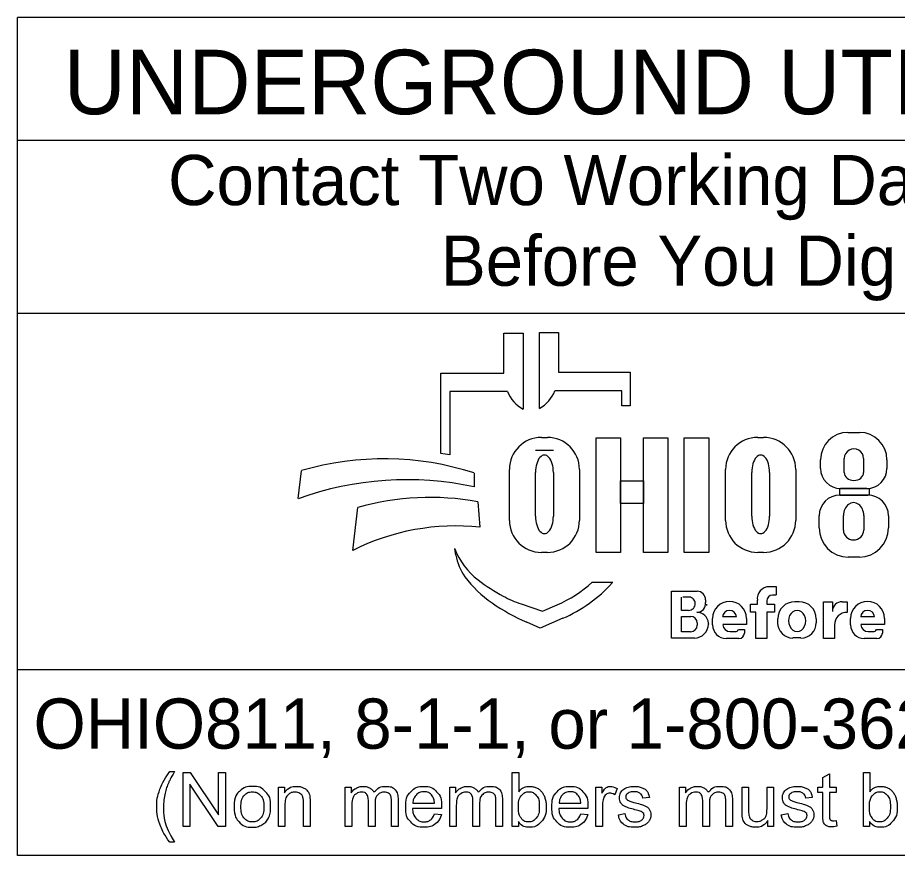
# Model space of a CAD drawing. Extents: x 0 to 34, y 0 to 22.
# Drawn here: x 14.876 to 17.33, y 5.729 to 8.066 of the extents above; entities that cross this region are included whole.
import ezdxf

# ---------------------------------------------------------------- set-up
doc = ezdxf.new("R2010")
doc.units = 0
doc.layers.add('GM_X_Adjacent_County', color=7, linetype='Continuous')
doc.layers.add('GM_X_Township', color=7, linetype='Continuous')

msp = doc.modelspace()

# ---------------------------------------------------------------- linework, layer by layer
at = {"layer": 'GM_X_Adjacent_County'}
for p, q in [((16.2322, 7.0744), (16.2322, 7.1859)), ((16.2322, 7.1859), (16.2858, 7.1859)), ((16.2858, 7.1859), (16.2858, 6.9738)), ((16.3315, 6.9761), (16.3315, 7.1882)), ((16.3315, 7.1882), (16.3851, 7.1882)), ((16.3851, 7.1882), (16.3851, 7.0767)), ((16.0562, 6.8505), (16.0562, 7.0744)), ((16.0562, 7.0744), (16.2322, 7.0744)), ((16.3851, 7.0767), (16.5844, 7.0767)), ((16.5844, 7.0767), (16.5844, 6.9829)), ((16.0815, 7.0229), (16.0815, 6.8461)), ((16.2426, 7.0229), (16.0815, 7.0229)), ((16.5611, 7.0253), (16.3747, 7.0253)), ((16.5611, 6.9829), (16.5611, 7.0253)), ((16.5844, 6.9829), (16.5611, 6.9829)), ((16.3372, 6.8952), (16.3537, 6.8952)), ((16.9402, 6.8952), (16.9568, 6.8952)), ((17.1918, 6.9092), (17.2245, 6.9092)), ((16.3705, 6.8582), (16.3207, 6.8582)), ((17.1155, 6.8086), (17.1155, 6.8329)), ((17.1816, 6.7972), (17.1816, 6.8365)), ((17.2358, 6.8365), (17.2358, 6.7972)), ((17.3008, 6.8329), (17.3008, 6.8086)), ((15.6589, 6.7242), (15.6683, 6.8023)), ((16.2477, 6.6637), (16.2477, 6.8057)), ((16.3206, 6.6751), (16.3206, 6.7975)), ((16.3704, 6.7975), (16.3704, 6.6751)), ((16.4432, 6.8057), (16.4432, 6.6637)), ((16.8508, 6.6637), (16.8508, 6.8057)), ((16.9237, 6.6751), (16.9237, 6.7975)), ((16.9735, 6.7975), (16.9735, 6.6751)), ((17.0462, 6.8057), (17.0462, 6.6637)), ((16.1495, 6.7958), (16.1495, 6.757)), ((17.2448, 6.7526), (17.1715, 6.7526)), ((17.1696, 6.7343), (17.247, 6.7343)), ((15.8107, 6.5797), (15.8254, 6.6998)), ((16.1595, 6.7152), (16.1657, 6.6443)), ((17.1118, 6.6424), (17.1118, 6.6764)), ((17.1792, 6.6364), (17.1792, 6.6773)), ((17.2361, 6.6773), (17.2361, 6.6364)), ((17.3049, 6.6764), (17.3049, 6.6424)), ((16.0984, 6.5668), (16.0953, 6.5847)), ((16.3537, 6.5743), (16.3372, 6.5743)), ((16.9568, 6.5743), (16.9402, 6.5743)), ((17.2239, 6.5614), (17.1927, 6.5614)), ((16.4787, 6.4909), (16.5361, 6.4909)), ((16.9726, 6.4787), (16.992, 6.4787)), ((16.992, 6.4787), (16.992, 6.4557)), ((16.7, 6.3351), (16.7, 6.4659)), ((16.7, 6.4659), (16.7712, 6.4659)), ((16.992, 6.4552), (16.9819, 6.4552)), ((16.2803, 6.4305), (16.3397, 6.41)), ((16.7279, 6.4124), (16.7279, 6.4493)), ((16.7531, 6.4493), (16.7319, 6.4493)), ((16.7949, 6.4421), (16.7949, 6.4342)), ((16.92, 6.4073), (16.92, 6.4303)), ((16.92, 6.4303), (16.9393, 6.4303)), ((16.9393, 6.4303), (16.9393, 6.4407)), ((16.9654, 6.4387), (16.9654, 6.4303)), ((16.9654, 6.4303), (16.9869, 6.4303)), ((16.9869, 6.4303), (16.9869, 6.4073)), ((17.0438, 6.4369), (17.0559, 6.4369)), ((17.124, 6.3339), (17.124, 6.4366)), ((17.124, 6.4366), (17.1486, 6.4366)), ((17.1486, 6.4366), (17.1486, 6.4098)), ((17.1758, 6.4366), (17.1897, 6.4366)), ((17.1897, 6.4366), (17.1897, 6.407)), ((16.3397, 6.41), (16.3807, 6.4278)), ((16.7474, 6.4124), (16.7279, 6.4124)), ((16.9349, 6.4073), (16.92, 6.4073)), ((16.9349, 6.3339), (16.9349, 6.4073)), ((16.9869, 6.4073), (16.9654, 6.4073)), ((16.9654, 6.4073), (16.9654, 6.3339)), ((16.3969, 6.3905), (16.3337, 6.363)), ((16.7279, 6.353), (16.7279, 6.3958)), ((16.7279, 6.3958), (16.7535, 6.3958)), ((16.8145, 6.3719), (16.8145, 6.3903)), ((16.8811, 6.3943), (16.8426, 6.3943)), ((16.9091, 6.3903), (16.9091, 6.3727)), ((16.996, 6.3782), (16.996, 6.389)), ((17.1037, 6.389), (17.1037, 6.3782)), ((17.1994, 6.3719), (17.1994, 6.3903)), ((17.266, 6.3943), (17.2275, 6.3943)), ((17.294, 6.3903), (17.294, 6.3727)), ((16.3337, 6.363), (16.2963, 6.3795)), ((16.7716, 6.3777), (16.7716, 6.3713)), ((16.803, 6.3748), (16.803, 6.3745)), ((16.9091, 6.3727), (16.8426, 6.3727)), ((16.8863, 6.359), (16.9031, 6.359)), ((16.9031, 6.359), (16.9031, 6.3492)), ((17.1545, 6.3721), (17.1545, 6.3339)), ((17.294, 6.3727), (17.2276, 6.3727)), ((17.2712, 6.359), (17.288, 6.359)), ((17.288, 6.359), (17.288, 6.3492)), ((16.7636, 6.3351), (16.7, 6.3351)), ((16.7532, 6.353), (16.7279, 6.353)), ((16.8879, 6.3339), (16.8525, 6.3339)), ((16.8636, 6.3534), (16.8777, 6.3534)), ((16.9654, 6.3339), (16.9349, 6.3339)), ((17.0609, 6.3355), (17.0387, 6.3355)), ((17.1545, 6.3339), (17.124, 6.3339)), ((17.2728, 6.3339), (17.2374, 6.3339)), ((17.2485, 6.3534), (17.2626, 6.3534))]:
    msp.add_line(p, q, dxfattribs=at)
for points in [[(16.4896, 6.8942), (16.5576, 6.8942), (16.5576, 6.5742), (16.4896, 6.5742)], [(16.6218, 6.8942), (16.6897, 6.8942), (16.6897, 6.5742), (16.6218, 6.5742)], [(16.7351, 6.8942), (16.8039, 6.8942), (16.8039, 6.5742), (16.7351, 6.5742)], [(16.5576, 6.7743), (16.6218, 6.7743), (16.6218, 6.7103), (16.5576, 6.7103)], [(17.1693, 6.7526), (17.251, 6.7526), (17.251, 6.7342), (17.1693, 6.7342)]]:
    msp.add_lwpolyline(points, close=True, dxfattribs=at)
for points in [[(15.3008, 5.9627), (15.314, 5.9627)], [(15.3375, 5.81), (15.3375, 5.9602), (15.3579, 5.9602), (15.4369, 5.8422), (15.4369, 5.9602), (15.4559, 5.9602), (15.4559, 5.81), (15.4355, 5.81), (15.3565, 5.928), (15.3565, 5.81), (15.3375, 5.81)], [(16.273, 5.81), (16.2559, 5.81), (16.2559, 5.9602), (16.2744, 5.9602), (16.2744, 5.9067)], [(17.1219, 5.8419), (17.1219, 5.9046), (17.1083, 5.9046), (17.1083, 5.9189), (17.1219, 5.9189), (17.1219, 5.9458), (17.1404, 5.9569), (17.1404, 5.9189), (17.1588, 5.9189), (17.1588, 5.9046), (17.1404, 5.9046), (17.1404, 5.8408)], [(17.2521, 5.81), (17.235, 5.81), (17.235, 5.9602), (17.2534, 5.9602), (17.2534, 5.9067)], [(15.6035, 5.81), (15.6035, 5.9189), (15.6201, 5.9189), (15.6201, 5.9034)], [(15.7899, 5.81), (15.7899, 5.9189), (15.8064, 5.9189), (15.8064, 5.9035)], [(16.0813, 5.81), (16.0813, 5.9189), (16.0978, 5.9189), (16.0978, 5.9035)], [(16.4891, 5.81), (16.4891, 5.9189), (16.5057, 5.9189), (16.5057, 5.9024)], [(16.5481, 5.9154), (16.5417, 5.8983)], [(16.7223, 5.81), (16.7223, 5.9189), (16.7388, 5.9189), (16.7388, 5.9035)], [(16.8966, 5.8515), (16.8966, 5.9189), (16.915, 5.9189), (16.915, 5.8585)], [(16.9663, 5.8606), (16.9663, 5.9189), (16.9847, 5.9189), (16.9847, 5.81), (16.9682, 5.81)], [(16.6381, 5.8907), (16.62, 5.8883)], [(17.0926, 5.8907), (17.0746, 5.8883)], [(15.6219, 5.8694), (15.6219, 5.81), (15.6035, 5.81)], [(15.6918, 5.8769), (15.6918, 5.81), (15.6734, 5.81), (15.6734, 5.8762)], [(15.8083, 5.8664), (15.8083, 5.81), (15.7899, 5.81)], [(15.873, 5.8732), (15.873, 5.81), (15.8546, 5.81), (15.8546, 5.8807)], [(15.9374, 5.8847), (15.9374, 5.81), (15.919, 5.81), (15.919, 5.8785)], [(15.9785, 5.8748), (16.0393, 5.8748)], [(16.0997, 5.8664), (16.0997, 5.81), (16.0813, 5.81)], [(16.1644, 5.8732), (16.1644, 5.81), (16.1459, 5.81), (16.1459, 5.8807)], [(16.2288, 5.8847), (16.2288, 5.81), (16.2104, 5.81), (16.2104, 5.8785)], [(16.3865, 5.8748), (16.4473, 5.8748)], [(16.5075, 5.867), (16.5075, 5.81), (16.4891, 5.81)], [(16.7407, 5.8664), (16.7407, 5.81), (16.7223, 5.81)], [(16.8054, 5.8732), (16.8054, 5.81), (16.7869, 5.81), (16.7869, 5.8807)], [(16.8698, 5.8847), (16.8698, 5.81), (16.8514, 5.81), (16.8514, 5.8785)], [(16.0587, 5.8597), (15.9775, 5.8597)], [(16.0391, 5.8452), (16.0581, 5.8428)], [(16.4666, 5.8597), (16.3855, 5.8597)], [(16.4471, 5.8452), (16.4661, 5.8428)], [(16.5517, 5.8425), (16.5699, 5.8454)], [(17.0062, 5.8425), (17.0244, 5.8454)], [(16.273, 5.8236), (16.273, 5.81)], [(16.9682, 5.81), (16.9682, 5.8261)], [(17.1588, 5.8265), (17.1614, 5.8102)], [(17.2521, 5.8236), (17.2521, 5.81)], [(15.314, 5.7658), (15.3008, 5.7658)]]:
    msp.add_lwpolyline(points, dxfattribs=at)
for centre, radius, start, end in [((16.334, 7.0597), 0.0985, 201.9296, 240.7469), ((16.2834, 7.062), 0.0985, 299.2531, 338.0704), ((16.3372, 6.8057), 0.0895, 90, 180), ((16.3537, 6.8057), 0.0895, 0, 90), ((16.9402, 6.8057), 0.0895, 90, 180), ((16.9568, 6.8057), 0.0895, 0, 90), ((17.1918, 6.8329), 0.0763, 90, 180), ((17.2245, 6.8329), 0.0763, 0, 90), ((15.9281, 6.0415), 0.8191, 79.2074, 81.0007), ((15.8983, 6.0163), 0.8191, 72.1402, 106.3144), ((17.1715, 6.8086), 0.056, 180, 270), ((17.2448, 6.8086), 0.056, 270, 0), ((15.9614, 5.8851), 0.8919, 77.8238, 109.8274), ((16.0253, 5.9955), 0.7322, 79.44, 105.8467), ((17.1696, 6.6764), 0.0579, 90, 180), ((17.247, 6.6764), 0.0579, 0, 90), ((16.3372, 6.6637), 0.0895, 180, 270), ((16.3537, 6.6637), 0.0895, 270, 0), ((16.9402, 6.6637), 0.0895, 180, 270), ((16.9568, 6.6637), 0.0895, 270, 0), ((16.0974, 6.0123), 0.6357, 83.8248, 116.8021), ((17.1927, 6.6424), 0.081, 180, 270), ((17.2239, 6.6424), 0.081, 270, 0), ((16.2827, 6.6568), 0.2008, 201.0457, 232.5314), ((16.2397, 6.5909), 0.1433, 189.6817, 216.0884), ((16.3734, 6.6883), 0.3088, 216.0884, 235.7167), ((16.4753, 6.908), 0.5173, 232.5314, 241.794), ((16.2373, 6.7583), 0.3602, 293.4582, 312.0712), ((16.2373, 6.7583), 0.401, 293.4582, 317.8286), ((16.9726, 6.4451), 0.0335, 90, 187.5187), ((16.7712, 6.4421), 0.0238, 0, 90), ((16.9819, 6.4387), 0.0165, 90, 180), ((16.5399, 6.9326), 0.6044, 235.7167, 246.2325), ((16.3901, 6.7492), 0.3371, 241.794, 250.9821), ((16.7474, 6.4311), 0.0187, 270, 2.0582), ((16.7492, 6.4324), 0.0169, 357.8325, 90), ((16.7708, 6.4314), 0.0243, 270, 6.6529), ((16.7813, 6.4299), 0.0175, 347.4023, 0), ((16.8618, 6.3903), 0.0473, 0, 180), ((17.0438, 6.389), 0.0478, 90, 180), ((17.0559, 6.389), 0.0478, 0, 90), ((17.1755, 6.4098), 0.0269, 89.2449, 180), ((17.2467, 6.3903), 0.0473, 0, 180), ((16.7709, 6.375), 0.0321, 4.0748, 90), ((16.8618, 6.3933), 0.0193, 2.9632, 177.0368), ((17.1895, 6.3721), 0.0349, 89.6033, 180), ((17.2468, 6.3933), 0.0193, 2.9632, 177.0368), ((16.7535, 6.3777), 0.0181, 0, 90), ((16.77, 6.3748), 0.033, 0, 11.7502), ((16.7532, 6.3713), 0.0184, 270, 0), ((16.7636, 6.3745), 0.0393, 270, 0), ((16.8525, 6.3719), 0.038, 180, 270), ((16.8636, 6.3744), 0.021, 184.827, 270), ((16.8777, 6.3628), 0.00938, 270, 335.9979), ((17.0387, 6.3782), 0.0428, 180, 270), ((17.0609, 6.3782), 0.0428, 270, 0), ((17.2374, 6.3719), 0.038, 180, 270), ((17.2485, 6.3744), 0.021, 184.827, 270), ((17.2626, 6.3628), 0.00938, 270, 335.9979), ((16.8879, 6.3492), 0.0152, 270, 0), ((17.2728, 6.3492), 0.0152, 270, 0)]:
    msp.add_arc(centre, radius, start, end, dxfattribs=at)
for centre, major_axis, ratio, start_param, end_param in [((17.2087, 6.8365), (0.0271, 0), 0.969373, 0, 3.141593), ((16.3455, 6.7975), (0, 0.0484), 0.514403, 4.712389, 7.853982), ((16.9486, 6.7975), (0, 0.0484), 0.514403, 4.712389, 7.853982), ((17.2087, 6.7972), (0.0271, 0), 0.818453, 3.141593, 6.283185), ((17.2077, 6.6773), (0, 0.0358), 0.794529, 4.712389, 7.853982), ((16.3455, 6.6751), (0, 0.0484), 0.514403, 1.570796, 4.712389), ((16.9486, 6.6751), (0, 0.0484), 0.514403, 1.570796, 4.712389), ((17.2077, 6.6364), (0.0284, 0), 0.959837, 3.141593, 6.283185), ((17.0503, 6.3836), (0, 0.029), 0.832186, 4.712389, 7.853982), ((17.0503, 6.3836), (0, 0.0302), 0.797287, 1.570796, 4.712389)]:
    msp.add_ellipse(centre, major_axis=major_axis, ratio=ratio, start_param=start_param, end_param=end_param, dxfattribs=at)
for points in [[(15.3008, 5.7658), (15.2855, 5.7851), (15.275, 5.8109), (15.2644, 5.8367), (15.2644, 5.8644), (15.2644, 5.8887), (15.2723, 5.9111), (15.2815, 5.937), (15.3008, 5.9627)], [(15.314, 5.9627), (15.3016, 5.9414), (15.2976, 5.9323), (15.2914, 5.9181), (15.2878, 5.9028), (15.2834, 5.8836), (15.2834, 5.8643), (15.2834, 5.815), (15.314, 5.7658)], [(15.48, 5.8644), (15.48, 5.8946), (15.4968, 5.9092), (15.5108, 5.9213), (15.531, 5.9213), (15.5534, 5.9213), (15.5676, 5.9066), (15.5819, 5.8919), (15.5819, 5.866), (15.5819, 5.845), (15.5756, 5.833), (15.5693, 5.8209), (15.5572, 5.8143), (15.5452, 5.8076), (15.531, 5.8076), (15.5082, 5.8076), (15.4941, 5.8223), (15.48, 5.8369), (15.48, 5.8644)], [(15.6201, 5.9034), (15.6321, 5.9213), (15.6547, 5.9213), (15.6645, 5.9213), (15.6728, 5.9177), (15.681, 5.9142), (15.6851, 5.9085), (15.6892, 5.9027), (15.6908, 5.8948), (15.6918, 5.8897), (15.6918, 5.8769)], [(15.8064, 5.9035), (15.8115, 5.9115), (15.82, 5.9164), (15.8285, 5.9213), (15.8394, 5.9213), (15.8515, 5.9213), (15.8592, 5.9162), (15.8669, 5.9112), (15.8701, 5.9022), (15.8831, 5.9213), (15.9038, 5.9213), (15.92, 5.9213), (15.9287, 5.9123), (15.9374, 5.9033), (15.9374, 5.8847)], [(16.0581, 5.8428), (16.0536, 5.8261), (16.0414, 5.8168), (16.0293, 5.8076), (16.0103, 5.8076), (15.9865, 5.8076), (15.9725, 5.8223), (15.9585, 5.837), (15.9585, 5.8635), (15.9585, 5.891), (15.9726, 5.9061), (15.9868, 5.9213), (16.0093, 5.9213), (16.0311, 5.9213), (16.0449, 5.9064), (16.0588, 5.8916), (16.0588, 5.8646), (16.0588, 5.863), (16.0587, 5.8597)], [(16.0978, 5.9035), (16.1029, 5.9115), (16.1114, 5.9164), (16.1199, 5.9213), (16.1308, 5.9213), (16.1428, 5.9213), (16.1506, 5.9162), (16.1583, 5.9112), (16.1615, 5.9022), (16.1744, 5.9213), (16.1951, 5.9213), (16.2114, 5.9213), (16.2201, 5.9123), (16.2288, 5.9033), (16.2288, 5.8847)], [(16.2744, 5.9067), (16.286, 5.9213), (16.3042, 5.9213), (16.3142, 5.9213), (16.3232, 5.9172), (16.3321, 5.9132), (16.3379, 5.9059), (16.3437, 5.8985), (16.347, 5.8882), (16.3502, 5.8778), (16.3502, 5.8661), (16.3502, 5.8381), (16.3364, 5.8229), (16.3226, 5.8076), (16.3032, 5.8076), (16.284, 5.8076), (16.273, 5.8236)], [(16.4661, 5.8428), (16.4616, 5.8261), (16.4494, 5.8168), (16.4373, 5.8076), (16.4183, 5.8076), (16.3944, 5.8076), (16.3805, 5.8223), (16.3665, 5.837), (16.3665, 5.8635), (16.3665, 5.891), (16.3806, 5.9061), (16.3948, 5.9213), (16.4173, 5.9213), (16.4391, 5.9213), (16.4529, 5.9064), (16.4667, 5.8916), (16.4667, 5.8646), (16.4667, 5.863), (16.4666, 5.8597)], [(16.5057, 5.9024), (16.512, 5.9139), (16.5174, 5.9176), (16.5227, 5.9213), (16.5292, 5.9213), (16.5385, 5.9213), (16.5481, 5.9154)], [(16.5699, 5.8454), (16.5714, 5.8344), (16.5784, 5.8286), (16.5855, 5.8227), (16.5981, 5.8227), (16.6109, 5.8227), (16.617, 5.8279), (16.6232, 5.8331), (16.6232, 5.8401), (16.6232, 5.8463), (16.6177, 5.8499), (16.6139, 5.8524), (16.5989, 5.8562), (16.5786, 5.8613), (16.5707, 5.865), (16.5629, 5.8688), (16.5588, 5.8754), (16.5548, 5.882), (16.5548, 5.8899), (16.5548, 5.8972), (16.5581, 5.9034), (16.5614, 5.9096), (16.5672, 5.9137), (16.5715, 5.9169), (16.5789, 5.9191), (16.5864, 5.9213), (16.5949, 5.9213), (16.6077, 5.9213), (16.6174, 5.9176), (16.6271, 5.9139), (16.6317, 5.9076), (16.6363, 5.9013), (16.6381, 5.8907)], [(16.7388, 5.9035), (16.7439, 5.9115), (16.7524, 5.9164), (16.7609, 5.9213), (16.7718, 5.9213), (16.7838, 5.9213), (16.7916, 5.9162), (16.7993, 5.9112), (16.8025, 5.9022), (16.8154, 5.9213), (16.8361, 5.9213), (16.8524, 5.9213), (16.8611, 5.9123), (16.8698, 5.9033), (16.8698, 5.8847)], [(17.0244, 5.8454), (17.026, 5.8344), (17.033, 5.8286), (17.04, 5.8227), (17.0527, 5.8227), (17.0654, 5.8227), (17.0716, 5.8279), (17.0778, 5.8331), (17.0778, 5.8401), (17.0778, 5.8463), (17.0723, 5.8499), (17.0685, 5.8524), (17.0534, 5.8562), (17.0331, 5.8613), (17.0253, 5.865), (17.0174, 5.8688), (17.0134, 5.8754), (17.0093, 5.882), (17.0093, 5.8899), (17.0093, 5.8972), (17.0127, 5.9034), (17.016, 5.9096), (17.0217, 5.9137), (17.026, 5.9169), (17.0335, 5.9191), (17.0409, 5.9213), (17.0494, 5.9213), (17.0623, 5.9213), (17.072, 5.9176), (17.0817, 5.9139), (17.0863, 5.9076), (17.0909, 5.9013), (17.0926, 5.8907)], [(17.2534, 5.9067), (17.2651, 5.9213), (17.2832, 5.9213), (17.2933, 5.9213), (17.3022, 5.9172), (17.3112, 5.9132), (17.317, 5.9059), (17.3228, 5.8985), (17.326, 5.8882), (17.3293, 5.8778), (17.3293, 5.8661), (17.3293, 5.8381), (17.3155, 5.8229), (17.3016, 5.8076), (17.2823, 5.8076), (17.263, 5.8076), (17.2521, 5.8236)], [(15.499, 5.8644), (15.499, 5.8435), (15.5081, 5.8331), (15.5172, 5.8227), (15.531, 5.8227), (15.5447, 5.8227), (15.5538, 5.8332), (15.5629, 5.8436), (15.5629, 5.865), (15.5629, 5.8852), (15.5537, 5.8956), (15.5446, 5.906), (15.531, 5.906), (15.5172, 5.906), (15.5081, 5.8957), (15.499, 5.8853), (15.499, 5.8644)], [(15.6734, 5.8762), (15.6734, 5.8874), (15.6713, 5.893), (15.6691, 5.8986), (15.6636, 5.9019), (15.6582, 5.9052), (15.6508, 5.9052), (15.639, 5.9052), (15.6305, 5.8978), (15.6219, 5.8903), (15.6219, 5.8694)], [(15.8546, 5.8807), (15.8546, 5.893), (15.8501, 5.8991), (15.8455, 5.9052), (15.8353, 5.9052), (15.8275, 5.9052), (15.8209, 5.9011), (15.8143, 5.897), (15.8113, 5.8892), (15.8083, 5.8813), (15.8083, 5.8664)], [(15.919, 5.8785), (15.919, 5.8896), (15.9172, 5.8944), (15.9154, 5.8993), (15.9107, 5.9023), (15.906, 5.9052), (15.8996, 5.9052), (15.8882, 5.9052), (15.8806, 5.8976), (15.873, 5.89), (15.873, 5.8732)], [(16.0393, 5.8748), (16.0381, 5.8886), (16.0323, 5.8955), (16.0235, 5.9062), (16.0095, 5.9062), (15.9968, 5.9062), (15.9881, 5.8976), (15.9795, 5.8891), (15.9785, 5.8748)], [(16.1459, 5.8807), (16.1459, 5.893), (16.1414, 5.8991), (16.1369, 5.9052), (16.1267, 5.9052), (16.1189, 5.9052), (16.1123, 5.9011), (16.1056, 5.897), (16.1027, 5.8892), (16.0997, 5.8813), (16.0997, 5.8664)], [(16.2104, 5.8785), (16.2104, 5.8896), (16.2086, 5.8944), (16.2068, 5.8993), (16.2021, 5.9023), (16.1974, 5.9052), (16.191, 5.9052), (16.1795, 5.9052), (16.1719, 5.8976), (16.1644, 5.89), (16.1644, 5.8732)], [(16.2728, 5.8653), (16.2728, 5.8457), (16.2781, 5.837), (16.2868, 5.8227), (16.3016, 5.8227), (16.3137, 5.8227), (16.3225, 5.8332), (16.3312, 5.8437), (16.3312, 5.8645), (16.3312, 5.8859), (16.3228, 5.896), (16.3144, 5.9062), (16.3024, 5.9062), (16.2903, 5.9062), (16.2816, 5.8956), (16.2728, 5.8851), (16.2728, 5.8653)], [(16.4473, 5.8748), (16.4461, 5.8886), (16.4403, 5.8955), (16.4315, 5.9062), (16.4175, 5.9062), (16.4048, 5.9062), (16.3961, 5.8976), (16.3874, 5.8891), (16.3865, 5.8748)], [(16.5417, 5.8983), (16.5349, 5.9023), (16.5282, 5.9023), (16.5222, 5.9023), (16.5174, 5.8986), (16.5126, 5.895), (16.5106, 5.8885), (16.5075, 5.8787), (16.5075, 5.867)], [(16.62, 5.8883), (16.6188, 5.8967), (16.6129, 5.9014), (16.607, 5.9062), (16.5962, 5.9062), (16.5835, 5.9062), (16.578, 5.9019), (16.5726, 5.8977), (16.5726, 5.8921), (16.5726, 5.8885), (16.5749, 5.8856), (16.5771, 5.8827), (16.5819, 5.8807), (16.5847, 5.8797), (16.5982, 5.876), (16.6178, 5.8708), (16.6256, 5.8674), (16.6333, 5.8641), (16.6378, 5.8578), (16.6422, 5.8514), (16.6422, 5.842), (16.6422, 5.8328), (16.6368, 5.8247), (16.6314, 5.8165), (16.6212, 5.8121), (16.6111, 5.8076), (16.5983, 5.8076), (16.577, 5.8076), (16.5659, 5.8164), (16.5547, 5.8252), (16.5517, 5.8425)], [(16.7869, 5.8807), (16.7869, 5.893), (16.7824, 5.8991), (16.7779, 5.9052), (16.7677, 5.9052), (16.7599, 5.9052), (16.7533, 5.9011), (16.7466, 5.897), (16.7437, 5.8892), (16.7407, 5.8813), (16.7407, 5.8664)], [(16.8514, 5.8785), (16.8514, 5.8896), (16.8496, 5.8944), (16.8478, 5.8993), (16.8431, 5.9023), (16.8384, 5.9052), (16.832, 5.9052), (16.8205, 5.9052), (16.8129, 5.8976), (16.8054, 5.89), (16.8054, 5.8732)], [(17.0746, 5.8883), (17.0733, 5.8967), (17.0674, 5.9014), (17.0615, 5.9062), (17.0508, 5.9062), (17.038, 5.9062), (17.0326, 5.9019), (17.0272, 5.8977), (17.0272, 5.8921), (17.0272, 5.8885), (17.0294, 5.8856), (17.0317, 5.8827), (17.0365, 5.8807), (17.0393, 5.8797), (17.0528, 5.876), (17.0724, 5.8708), (17.0802, 5.8674), (17.0879, 5.8641), (17.0923, 5.8578), (17.0968, 5.8514), (17.0968, 5.842), (17.0968, 5.8328), (17.0914, 5.8247), (17.086, 5.8165), (17.0758, 5.8121), (17.0657, 5.8076), (17.0528, 5.8076), (17.0316, 5.8076), (17.0204, 5.8164), (17.0093, 5.8252), (17.0062, 5.8425)], [(17.2518, 5.8653), (17.2518, 5.8457), (17.2571, 5.837), (17.2658, 5.8227), (17.2807, 5.8227), (17.2927, 5.8227), (17.3015, 5.8332), (17.3103, 5.8437), (17.3103, 5.8645), (17.3103, 5.8859), (17.3019, 5.896), (17.2934, 5.9062), (17.2815, 5.9062), (17.2694, 5.9062), (17.2606, 5.8956), (17.2518, 5.8851), (17.2518, 5.8653)], [(15.9775, 5.8597), (15.9785, 5.8418), (15.9876, 5.8322), (15.9968, 5.8227), (16.0104, 5.8227), (16.0205, 5.8227), (16.0277, 5.8281), (16.0349, 5.8334), (16.0391, 5.8452)], [(16.3855, 5.8597), (16.3865, 5.8418), (16.3956, 5.8322), (16.4048, 5.8227), (16.4184, 5.8227), (16.4285, 5.8227), (16.4357, 5.8281), (16.4429, 5.8334), (16.4471, 5.8452)], [(16.9682, 5.8261), (16.9555, 5.8076), (16.9337, 5.8076), (16.9241, 5.8076), (16.9158, 5.8113), (16.9074, 5.815), (16.9034, 5.8206), (16.8994, 5.8262), (16.8977, 5.8342), (16.8966, 5.8397), (16.8966, 5.8515)], [(16.915, 5.8585), (16.915, 5.8441), (16.9161, 5.8391), (16.9179, 5.8318), (16.9235, 5.8277), (16.9291, 5.8235), (16.9374, 5.8235), (16.9457, 5.8235), (16.953, 5.8278), (16.9603, 5.832), (16.9633, 5.8393), (16.9663, 5.8467), (16.9663, 5.8606)], [(17.1614, 5.8102), (17.1536, 5.8085), (17.1475, 5.8085), (17.1375, 5.8085), (17.132, 5.8117), (17.1264, 5.8149), (17.1242, 5.8201), (17.1219, 5.8253), (17.1219, 5.8419)], [(17.1404, 5.8408), (17.1404, 5.8329), (17.1413, 5.8306), (17.1423, 5.8284), (17.1445, 5.827), (17.1467, 5.8257), (17.1507, 5.8257), (17.1538, 5.8257), (17.1588, 5.8265)]]:
    msp.add_open_spline(points, degree=3, dxfattribs=at)
at = {"layer": 'GM_X_Township'}
for p, q in [((14.8762, 5.7289), (14.8762, 8.0664)), ((19.1262, 8.0664), (14.8762, 8.0664)), ((14.8762, 7.7248), (19.1262, 7.7248)), ((14.8762, 7.2414), (19.1262, 7.2414)), ((19.1262, 6.2468), (14.8762, 6.2468)), ((19.1262, 5.7289), (14.8762, 5.7289))]:
    msp.add_line(p, q, dxfattribs=at)

# ---------------------------------------------------------------- texts
at = {"layer": 'GM_X_Adjacent_County'}
for s, height, p in [('UNDERGROUND UTILITIES', 0.18, (15.0043, 7.7967)), ('Contact Two Working Days', 0.14, (15.2958, 7.5432)), ('Before You Dig', 0.14, (16.057, 7.3182)), ('OHIO811, 8-1-1, or 1-800-362-2764', 0.14, (14.9206, 6.0267))]:
    msp.add_text(s, height=height, dxfattribs=at).set_placement(p)

doc.saveas('drawing.dxf')
